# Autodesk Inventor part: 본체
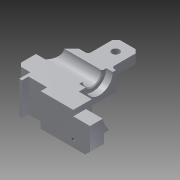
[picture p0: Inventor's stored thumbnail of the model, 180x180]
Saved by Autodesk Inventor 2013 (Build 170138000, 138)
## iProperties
Created: 2016-11
Part Number: 본체
Material: 알루미늄 6061
Document SubType Name: Modeling
Designer: Administrator
Density: 2.71 g/cm^3
Mass: 462.696 g
Surface Area: 317.767 cm^2
Volume: 170.737 cm^3
Author: Administrator
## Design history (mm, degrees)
sketch "스케치1"
  geometry: L1 (0, 0)-(58, 0); L2 (58, 0)-(58, 48); L3 (58, 48)-(0, 48); L4 (0, 48)-(0, 0)
  constraints: 8 end point, 2 parallel, 1 horizontal, 1 perpendicular
  dimensions: "d0" = 48 distance between parallel lines of L1 L3; "d2" = 58 distance of L1.start L1.end
extrude "돌출1" new body sketch "스케치1" stored distance "d3" = 40; taper "d4" = 0 deg
sketch "스케치2"
  geometry: L1 (0, 0)-(0, 48) reference; L2 (0, 48)-(58, 48) reference; L3 (58, 48)-(58, 0) reference; L4 (58, 0)-(0, 0) reference; L5 (14, 3)-(90, 3); L6 (90, 3)-(90, -12); L7 (90, -12)-(14, -12); L8 (14, -12)-(14, 3); C1 r 13 at (27, 3)
  constraints: 8 end point, 2 parallel, 1 centre point, 1 horizontal, 1 perpendicular, 1 point on line, 1 tangent
  dimensions: "d5" = 76 distance of L6.end L7.end; "d7" = 15 distance between parallel lines of L7 L5; "d8" = 90 distance between parallel lines of L6 L1; "d9" = 60 distance between parallel lines of L7 L2; "d10" = 26 diameter of C1
extrude "돌출2" join sketch "스케치2" stored distance "d11" = 70; taper "d12" = 0 deg
sketch "스케치3"
  geometry: L1 (0, 0)-(0, 48) reference; L2 (0, 48)-(58, 48) reference; L3 (58, 48)-(58, 3) reference; L4 (58, 3)-(90, 3) reference; L5 (90, 3)-(90, -12) reference; L6 (90, -12)-(14, -12) reference; L7 (14, -12)-(14, 0) reference; L8 (14, 0)-(0, 0) reference; L9 (58, 48)-(58, 3) reference; L10 (90, -12)-(58, -12); L11 (58, -12)-(58, 8); L12 (58, 8)-(90, 8); L13 (90, 8)-(90, -12)
  constraints: 8 end point, 2 parallel, 1 horizontal, 1 perpendicular, 1 point on line
  dimensions: "d13" = 20 distance between parallel lines of L10 L12
extrude "돌출3" join sketch "스케치3" stored distance "d15" = 40; taper "d16" = 0 deg
sketch "스케치4"
  geometry: L1 (14, 3)-(14, -12) reference; L2 (14, -12)-(90, -12) reference; L3 (90, -12)-(14, -12) reference; L4 (17, -5)-(37, -5); L5 (37, -5)-(37, -12); L6 (37, -12)-(17, -12); L7 (17, -12)-(17, -5); 1 further point
  constraints: 8 end point, 2 parallel, 1 horizontal, 1 perpendicular, 1 point on line
  dimensions: "d17" = 3 distance between parallel lines of L1 L7; "d18" = 7 distance between parallel lines of L2 L4; "d19" = 20 distance between parallel lines of L7 L5
extrude "돌출4" cut sketch "스케치4" stored distance "d20" = 40; taper "d21" = 0 deg
sketch "스케치5"
  geometry: L1 (0, 0)-(0, 48) reference; L2 (0, 48)-(58, 48) reference; L3 (58, 48)-(58, 8) reference; L4 (58, 8)-(90, 8) reference; L5 (90, 8)-(90, -12) reference; L6 (90, -12)-(37, -12) reference; L7 (37, -12)-(37, -5) reference; L8 (37, -5)-(17, -5) reference; L9 (17, -5)-(17, -12) reference; L10 (17, -12)-(14, -12) reference; L11 (14, -12)-(14, 0) reference; L12 (14, 0)-(0, 0) reference; L13 (28, 78)-(53, 78); L14 (53, 78)-(53, 48); L15 (53, 48)-(28, 48); L16 (28, 48)-(28, 78); L17 (40.5, 78)-(40.5, 48); L18 (0, 48)-(58, 48) reference
  constraints: 10 end point, 2 parallel, 2 perpendicular, 2 point on line, 1 horizontal, 1 midpoint
  dimensions: "d22" = 5 distance between parallel lines of L3 L14; "d23" = 25 distance between parallel lines of L14 L16; "d24" = 12.5 distance between parallel lines of L16 L17 (derived); "d25" = 90 distance between parallel lines of L6 L13
extrude "돌출5" join sketch "스케치5" stored distance "d26" = 20; taper "d27" = 0 deg
sketch "스케치6"
  geometry: L1 (0, 0)-(0, 48) reference; L2 (0, 48)-(28, 48) reference; L3 (28, 48)-(28, 78) reference; L4 (28, 78)-(53, 78) reference; L5 (53, 78)-(53, 48) reference; L6 (53, 48)-(58, 48) reference; L7 (58, 48)-(58, 8) reference; L8 (58, 8)-(90, 8) reference; L9 (90, 8)-(90, -12) reference; L10 (90, -12)-(37, -12) reference; L11 (37, -12)-(37, -5) reference; L12 (37, -5)-(17, -5) reference; L13 (17, -5)-(17, -12) reference; L14 (17, -12)-(14, -12) reference; L15 (14, -12)-(14, 0) reference; L16 (14, 0)-(0, 0) reference; L17 (0, 0)-(0, 48) reference; L18 (0, 40)-(51, 40); L19 (58, 44.5)-(58, 30); L20 (0, 30)-(0, 40); L21 (51, 40)-(51, 44.5); L22 (51, 44.5)-(58, 44.5); L23 (0, 30)-(58, 30); L24 (58, 48)-(58, 8) reference
  constraints: 12 end point, 4 point on line, 3 perpendicular, 2 parallel, 1 horizontal
  dimensions: "d31" = 7 distance between parallel lines of L19 L21; "d32" = 30 distance between parallel lines of L16 L23; "d33" = 29 diameter of L22 L23; "d34" = 20 diameter of L18 L23
revolve "회전1" sketch "스케치6" stored, may be unused: angle "d35" = 90 deg
chamfer "모따기1" distance "d36" = 18; stored, may be unused: second distance "d37" = 2, angle "d38" = 45 deg
chamfer "모따기2" distance "d39" = 1; stored, may be unused: second distance "d40" = 2, angle "d41" = 45 deg
chamfer "모따기3" distance "d42" = 4; stored, may be unused: second distance "d43" = 2, angle "d44" = 45 deg
fillet "모깎기1" dims "d45" = 3
sketch "스케치8"
  geometry: L1 (0, 0)-(70, 0) reference; L2 (55, 20)-(15, 20) reference; L3 (29, 13.627)-(29, 0); L4 (0, 0)-(70, 0) reference; L5 (41, 13.627)-(41, 0); L6 (16.106, 20)-(53.894, 20); L7 (15, 20)-(55, 20) reference; L8 (29, 0)-(41, 0); C1 r 14.5 at (35, 42) reference; A1 r 29 centre (35, 42) between (16.106, 20) and (53.894, 20); 1 further point
  constraints: 8 end point, 4 point on circle, 4 point on line, 2 collinear, 2 perpendicular, 1 centre point, 1 coincident
  dimensions: "d56" = 12 distance between parallel lines of L5 L3; "d57" = 6 distance from line of L3 point (35, 12); "d97" = 29 radius of A1
extrude "돌출7" cut sketch "스케치8" distance "d58" = 18; taper "d59" = 0 deg
chamfer "모따기5" distance "d60" = 5; stored, may be unused: second distance "d61" = 2, angle "d62" = 45 deg
fillet "모깎기2" dims "d63" = 5
node "작업 평면1"
sketch "스케치9"
  geometry: L1 (0, 0)-(0, 10) reference; 2 further points
  dimensions: "d64" = 18 distance from line of L1 point (-18, 2.5); "d68" = 27.5 vertical distance of point (-18, 2.5) point (-90, 30)
hole "구멍1" sketch "스케치9" at (-18, 2.5) diameter "d71" = 3.242; stored, may be unused: countersink angle "d75" = 90 deg, drill point angle "d77" = 118 deg; dims "d72" = 6, "d73" = 4, "d74" = 2, "d76" = 8
node "작업 평면2"
sketch "스케치10"
  geometry: L1 (58, 8)-(58, 48) reference; L2 (58, 48)-(18, 48) reference; 2 further points
  constraints: 1 other
  dimensions: "d78" = 25 distance from line of L1 point (33, 30); "d79" = 18 distance from line of point (33, 30) L2
feature "엠보싱1" sketch "스케치10" dims "d0" = 48, "d2" = 58, "d80" = 0.5, "d81" = 0
sketch "스케치11"
  geometry: L1 (28, 74)-(28, 51) reference; L2 (14, -12)-(14, 0) reference; L3 (14, 0)-(0, 0) reference; L4 (0, 0)-(0, 30) reference; L5 (0, 30)-(18, 48) reference; L6 (18, 48)-(25, 48) reference; L7 (28, 51)-(28, 74) reference; L8 (28, 74)-(32, 78) reference; L9 (32, 78)-(49, 78) reference; L10 (49, 78)-(53, 74) reference; L11 (53, 74)-(53, 51) reference; L12 (56, 48)-(58, 48) reference; L13 (58, 48)-(58, 40.5) reference; L14 (58, 40.5)-(51, 40.5) reference; L15 (51, 40.5)-(51, 34.583) reference; L16 (0, 30)-(50, 30) reference; L17 (17, -12)-(14, -12) reference; L18 (17, -5)-(17, -12) reference; L19 (37, -5)-(17, -5) reference; L20 (37, -12)-(37, -5) reference; L21 (90, -12)-(37, -12) reference; L22 (90, 2.779)-(90, -12) reference; L23 (72, 2.779)-(90, 2.779) reference; L24 (72, 8)-(72, 2.779) reference; L25 (58, 8)-(72, 8) reference; L26 (58, 19.5)-(58, 8) reference; L27 (51, 19.5)-(58, 19.5) reference; L28 (51, 25.417)-(51, 19.5) reference; L29 (25, 48)-(56, 48) reference; A1 r 3 centre (25, 51) between (25, 48) and (28, 51) reference; A2 r 3 centre (56, 51) between (53, 51) and (56, 48) reference; 1 further point
  constraints: 2 other
  dimensions: "d82" = 35 distance from line of point (40.5, 65) L16; "d83" = 12.5 distance from line of L1 point (40.5, 65)
hole "구멍2" sketch "스케치11" at (40.5, 65) diameter "d84" = 8; stored, may be unused: countersink angle "d88" = 90 deg, drill point angle "d90" = 118 deg; dims "d85" = 6, "d86" = 4, "d87" = 2, "d89" = 8
chamfer "모따기7" distance "d94" = 1; stored, may be unused: second distance "d95" = 2, angle "d96" = 45 deg
chamfer "모따기8" distance "d98" = 4; stored, may be unused: second distance "d99" = 2, angle "d100" = 45 deg
sketch "스케치13"
  geometry: L1 (0, 53.796)-(37.759, 53.796); L2 (37.759, 53.796)-(37.759, -50.089); L3 (37.759, -50.089)-(0, -50.089); L4 (0, -50.089)-(0, 53.796); A1 r 10 centre (0, 0) between (-10, 0) and (10, 0) reference; 1 further point
  constraints: 8 end point, 2 parallel, 1 horizontal, 1 perpendicular, 1 point on line
extrude "돌출9" cut sketch "스케치13" stored distance "d103" = 10; taper "d104" = 0 deg
node "솔리드1"
mirror "대칭1"
node "절단 모서리 투영1"
node "절단 모서리 투영2"
node "절단 모서리 투영3"
node "절단 모서리 투영4"
node "절단 모서리 투영6"
